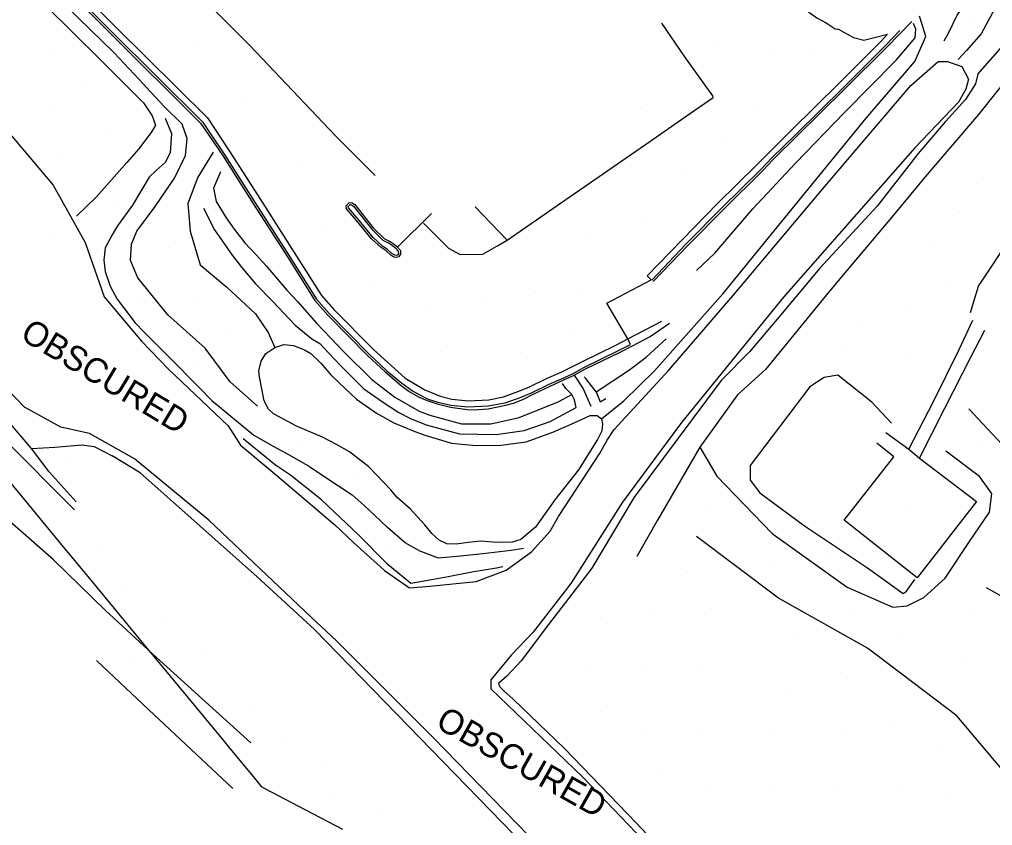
# Model space of a CAD drawing. Extents: x 1497074 to 1501343, y 481943 to 486114.
# Drawn here: x 1497639.7 to 1497875.9, y 483492.4 to 483688.1 of the extents above; entities that cross this region are included whole.
import ezdxf

# ---------------------------------------------------------------- set-up
doc = ezdxf.new("R2010")
doc.units = 0
for name, color, linetype in [('PH Exist DTM Boundary', 7, 'Continuous'), ('PH Exist DTM Breakline', 7, 'Continuous'), ('PH Exist DTM Obscure Area', 7, 'Continuous'), ('PH Exist DTM Obscure Area Text', 7, 'Continuous'), ('PH Exist DTM Point', 7, 'Continuous')]:
    doc.layers.add(name, color=color, linetype=linetype)

msp = doc.modelspace()

# ---------------------------------------------------------------- linework, layer by layer
at = {"layer": 'PH Exist DTM Boundary'}
msp.add_lwpolyline([(1497635.54, 483577.94), (1497640.86, 483571.49), (1497649.09, 483561.53), (1497657.38, 483551.49), (1497669.09, 483537.31), (1497673.9, 483531.49), (1497689.09, 483513.09), (1497690.41, 483511.49), (1497696.7, 483503.88), (1497698.36, 483501.87), (1497698.36, 483501.87), (1497699.1, 483501.48), (1497709.09, 483496.24), (1497718.13, 483491.49)], dxfattribs=at)
at = {"layer": 'PH Exist DTM Breakline'}
for points in [[(1497575.83, 483754.04), (1497585.07, 483744.96), (1497586.7, 483743.97), (1497599.88, 483735.61), (1497612.14, 483727.98), (1497626.37, 483719.13), (1497635.77, 483713.32), (1497637.64, 483711.74), (1497647, 483702.5), (1497663.02, 483686.34), (1497685.28, 483664.21), (1497687.33, 483661.17), (1497690.78, 483656.02), (1497698.2, 483644.4), (1497706.4, 483631.54), (1497713.02, 483621.1), (1497716.03, 483617.69), (1497725.66, 483608.02), (1497733.35, 483601.07), (1497738.1, 483598.17), (1497741.83, 483596.62)], [(1497562.72, 483753.21), (1497568.33, 483746.83), (1497576.49, 483734.94), (1497585.28, 483728.36), (1497589.95, 483725), (1497595.77, 483721.16), (1497600.07, 483718.96), (1497608.17, 483715.58), (1497619.96, 483710.5), (1497628.08, 483707.35), (1497634.62, 483702.1), (1497645.91, 483691.6), (1497659.31, 483678.33), (1497669.77, 483667.86), (1497671.91, 483664.72), (1497672.72, 483662.5), (1497671.65, 483660.67), (1497668.57, 483656.64), (1497665.77, 483653.41)], [(1497574.43, 483752.61), (1497583.83, 483743.37), (1497585.65, 483742.27), (1497598.81, 483733.92), (1497611.09, 483726.28), (1497625.31, 483717.43), (1497634.59, 483711.7), (1497636.29, 483710.26), (1497645.59, 483701.09), (1497661.58, 483684.88), (1497683.66, 483662.93), (1497685.67, 483660.06), (1497689.1, 483654.93), (1497696.51, 483643.32), (1497704.71, 483630.47), (1497711.41, 483619.89), (1497714.57, 483616.32), (1497724.23, 483606.49), (1497728.48, 483602.58), (1497732.36, 483599.27), (1497734.32, 483597.83), (1497736.71, 483596.39), (1497738.66, 483595.59), (1497741.06, 483594.77)], [(1497574.78, 483752.97), (1497584.14, 483743.77), (1497585.91, 483742.7), (1497599.08, 483734.34), (1497611.35, 483726.71), (1497625.58, 483717.86), (1497634.89, 483712.1), (1497636.63, 483710.63), (1497645.94, 483701.44), (1497661.96, 483685.28), (1497684.12, 483663.25), (1497686.08, 483660.34), (1497689.52, 483655.2), (1497696.93, 483643.59), (1497705.14, 483630.73), (1497711.82, 483620.2), (1497714.93, 483616.66), (1497724.58, 483606.85), (1497728.82, 483602.83), (1497732.45, 483599.86), (1497735.09, 483597.98), (1497736.41, 483597.24), (1497738.92, 483595.97), (1497741.25, 483595.24)], [(1497573.64, 483748.1), (1497579.34, 483742.98), (1497587.28, 483736.34), (1497594.04, 483732.42), (1497603.79, 483726.42), (1497613.64, 483720.18), (1497622.91, 483714.91), (1497631.39, 483710.16), (1497639.16, 483703.89), (1497645.22, 483697.29), (1497653.88, 483688.51), (1497662.67, 483680.05), (1497668.76, 483673.59), (1497671.46, 483670.56)], [(1497648.71, 483730.85), (1497650.63, 483727.26), (1497671.76, 483705.81), (1497695.58, 483681.83), (1497716.37, 483659.88), (1497726.06, 483650.26)], [(1497822.93, 483707.95), (1497822.81, 483706.32), (1497824.27, 483704.15), (1497826.17, 483701.49), (1497826.69, 483700.35), (1497827.15, 483698.94), (1497827.87, 483697.45), (1497828.78, 483696.01), (1497829.79, 483694.47), (1497830.42, 483693.29), (1497830.64, 483692.17), (1497830.86, 483690.95), (1497831.3, 483689.86), (1497833.28, 483688.55), (1497834.47, 483687.88), (1497835.51, 483687.3), (1497837.67, 483685.85), (1497838.51, 483685.76), (1497839.63, 483685.13), (1497840.84, 483684.45), (1497842.15, 483683.72), (1497844.7, 483683.08), (1497846.93, 483683.68), (1497850.43, 483684.56)], [(1497864.16, 483682.92), (1497865.32, 483684.98), (1497867.34, 483689.2), (1497869.92, 483692.64), (1497875.5, 483699.15), (1497881.21, 483704.9), (1497885.39, 483706.21), (1497889.4, 483705.65), (1497893.37, 483703.52)], [(1497919.84, 483703.45), (1497916.87, 483699.5), (1497910.38, 483696.91), (1497902.91, 483696.72), (1497899.24, 483695.95), (1497894.07, 483691.67), (1497883.32, 483678.69), (1497872.48, 483665.05), (1497859.56, 483649.91), (1497851.77, 483640.5), (1497840.53, 483627.17), (1497836.36, 483622.13)], [(1497872.34, 483674.87), (1497879.53, 483683.03), (1497887.17, 483692.17), (1497892.8, 483698.81), (1497892.79, 483700.85), (1497891.93, 483702.11), (1497889.19, 483703.47), (1497886.19, 483703.42), (1497884.52, 483702.55), (1497883.4, 483701.73), (1497879.77, 483697.78), (1497877.06, 483691.88), (1497873.13, 483684.66), (1497869.6, 483680.61), (1497867.54, 483678.39)], [(1497780.96, 483591.16), (1497786.43, 483595.5), (1497793.83, 483602.79), (1497800.9, 483610.75), (1497810.53, 483621.57), (1497824.73, 483639.11), (1497845.24, 483664.15), (1497857.07, 483677.91), (1497859.68, 483683.97), (1497858.87, 483686.92), (1497858.2, 483688.91)], [(1497850.27, 483681.44), (1497856.32, 483687.67)], [(1497771.24, 483643.7), (1497792.74, 483658.47), (1497801.51, 483664.67), (1497808.08, 483669.22), (1497807.98, 483669.6), (1497801.17, 483679.02), (1497795.59, 483687.2)], [(1497804.02, 483627.14), (1497808.47, 483631.39), (1497817.74, 483642.14), (1497828.04, 483653.24), (1497839.99, 483665.51), (1497852.48, 483678.24), (1497857.14, 483683.65), (1497857.26, 483685.81), (1497856.74, 483687.15)], [(1497849.91, 483681.79), (1497853.4, 483685.46)], [(1497792.1, 483625.85), (1497800.56, 483634.64), (1497809.24, 483643.49), (1497818.61, 483652.76), (1497821.4, 483655.5), (1497827.12, 483661.26), (1497838.64, 483672.67), (1497848.85, 483682.85)], [(1497848.85, 483682.85), (1497850.43, 483684.56)], [(1497793.19, 483624.82), (1497801.57, 483633.63), (1497810.3, 483642.43), (1497819.68, 483651.71), (1497822.34, 483654.49), (1497828.17, 483660.19), (1497839.7, 483671.61), (1497849.91, 483681.79)], [(1497793.55, 483624.47), (1497801.93, 483633.28), (1497810.66, 483642.07), (1497820.04, 483651.36), (1497822.69, 483654.13), (1497828.52, 483659.84), (1497840.05, 483671.25), (1497850.27, 483681.44)], [(1497872.34, 483674.87), (1497871.78, 483672.46), (1497869.35, 483668.72), (1497864.53, 483663.34), (1497857.88, 483655.56), (1497847.87, 483642.82), (1497833.97, 483627.75), (1497824.05, 483615.85), (1497816.9, 483607.39), (1497810.05, 483600.45), (1497788.88, 483572.14), (1497778.63, 483554.89), (1497768.08, 483541.19), (1497761.44, 483532.36), (1497758.01, 483528.64), (1497756, 483526.9), (1497756.26, 483526.04), (1497757.26, 483525.07), (1497759.55, 483523.07), (1497771.97, 483511.13), (1497789.42, 483493.02), (1497805.35, 483476.14)], [(1497697.42, 483594.25), (1497690.79, 483600.17), (1497684.72, 483608.29), (1497675.69, 483616.38), (1497668.38, 483625.42), (1497666.64, 483629.57), (1497666.87, 483633.56), (1497668.17, 483636.72), (1497672.58, 483642.72), (1497677.31, 483649.62), (1497679.97, 483655.12), (1497680.36, 483659.19), (1497679.13, 483662.71), (1497674.88, 483666.95), (1497671.46, 483670.56)], [(1497675.02, 483664.15), (1497676.55, 483660.43), (1497676.23, 483655.77), (1497675.01, 483653.38), (1497672.87, 483651.44), (1497671.12, 483649.85), (1497667.14, 483643.05), (1497663.49, 483638.04), (1497662.14, 483635.84), (1497660.47, 483632.66), (1497660.12, 483629.67), (1497660.51, 483626.94), (1497661.7, 483623.38), (1497663.41, 483620.18), (1497667.79, 483614.43), (1497669.98, 483612.19), (1497675.96, 483606.23), (1497683.3, 483598.8), (1497686.39, 483595.58), (1497696.53, 483587.21), (1497701.23, 483584.55), (1497705.11, 483582.39), (1497710.06, 483579.59), (1497713.56, 483577.26), (1497720.45, 483572.68), (1497723.38, 483570.09), (1497725.78, 483567.84)], [(1497686.66, 483655.94), (1497682.95, 483649.86), (1497680.51, 483643.44), (1497681.15, 483636.72), (1497683.56, 483628.54), (1497690, 483623.09), (1497696.96, 483616.63), (1497700.02, 483612.12), (1497701.63, 483608.46)], [(1497653.51, 483640.38), (1497658.38, 483645.08), (1497665.77, 483653.41)], [(1497688.51, 483651.11), (1497686.76, 483647.2), (1497687.42, 483643.93), (1497689.87, 483639.95), (1497691.79, 483637.2), (1497694.41, 483633.91), (1497697.14, 483631), (1497699.54, 483628.28), (1497704.6, 483622.39), (1497707.24, 483619.6), (1497709.42, 483617.02), (1497711.82, 483614.36), (1497715.15, 483610.83), (1497718.37, 483607.52), (1497725.25, 483600.71), (1497730.77, 483596.38), (1497736.69, 483593.03), (1497739.33, 483592.03)], [(1497870.59, 483616.98), (1497872.49, 483623.34), (1497881.01, 483636.16), (1497893.02, 483647.38), (1497893.99, 483648.02), (1497908.7, 483636.14), (1497915.18, 483630.74)], [(1497727.48, 483632.76), (1497725.17, 483634.88), (1497721.48, 483639.29), (1497719.07, 483642.15), (1497718.98, 483642.89), (1497719.75, 483643.69), (1497720.43, 483643.61), (1497721.1, 483643.21), (1497725.56, 483637.56), (1497728.22, 483634.92), (1497729.4, 483634.3)], [(1497727.82, 483633.12), (1497725.54, 483635.22), (1497721.87, 483639.61), (1497719.55, 483642.36), (1497719.5, 483642.72), (1497719.94, 483643.17), (1497720.27, 483643.13), (1497720.76, 483642.83), (1497725.18, 483637.23), (1497727.92, 483634.51), (1497729.16, 483633.86)], [(1497750.32, 483642.61), (1497758.09, 483634.57), (1497771.24, 483643.7)], [(1497653.03, 483569.03), (1497635.82, 483586.41), (1497626.83, 483594.18), (1497608.71, 483609.33), (1497587.1, 483627.01), (1497571.53, 483641.23)], [(1497684.34, 483642.29), (1497687.05, 483637.01), (1497691.31, 483630.92), (1497693.55, 483627.99), (1497697.01, 483623.95), (1497701.17, 483619.65), (1497706.64, 483613.88), (1497710.63, 483610.55), (1497712.62, 483609.42), (1497714.78, 483607.08), (1497717.49, 483604.19), (1497720.49, 483601.2), (1497723.3, 483598.47), (1497727.83, 483595.26), (1497731.76, 483592.73), (1497734.63, 483591.22), (1497738.37, 483589.73)], [(1497739.7, 483641.04), (1497731.42, 483632.83)], [(1497737.77, 483638.63), (1497743.82, 483632.63), (1497746.69, 483631.08), (1497752.16, 483631.15), (1497755.6, 483633.12), (1497758.09, 483634.57)], [(1497731.1, 483632.44), (1497730.13, 483633.26), (1497729.16, 483633.86)], [(1497731.42, 483632.83), (1497730.42, 483633.67), (1497729.4, 483634.3)], [(1497731.42, 483632.83), (1497732.14, 483632.02), (1497732.18, 483631.16), (1497731.74, 483630.49), (1497731.14, 483630.3), (1497730.58, 483630.41), (1497729.81, 483630.89), (1497728.71, 483631.91), (1497727.48, 483632.76)], [(1497731.1, 483632.44), (1497731.65, 483631.82), (1497731.67, 483631.3), (1497731.42, 483630.91), (1497731.11, 483630.82), (1497730.77, 483630.88), (1497730.11, 483631.29), (1497729.02, 483632.3), (1497727.82, 483633.12)], [(1497787.33, 483610.55), (1497782.31, 483619.23), (1497793.06, 483624.94)], [(1497793.06, 483624.94), (1497792.1, 483625.85)], [(1497836.36, 483622.13), (1497830.19, 483614.66), (1497820.83, 483603.11), (1497813.98, 483596.95), (1497804.83, 483584.31), (1497794.55, 483566.53), (1497789.53, 483557.76)], [(1497653.44, 483571.02), (1497646.88, 483578.26), (1497642.57, 483583.92), (1497636.49, 483591.1), (1497628.04, 483600.75), (1497622.39, 483606.96), (1497615.79, 483613.28), (1497609.03, 483619.16)], [(1497788.01, 483609.21), (1497787.33, 483610.55), (1497795.61, 483614.83)], [(1497788.47, 483608.87), (1497792.77, 483611.17), (1497797.49, 483614.38)], [(1497855.56, 483583.75), (1497861.62, 483595.35), (1497867.83, 483608.02), (1497871.17, 483615.1)], [(1497858.21, 483581.57), (1497864.32, 483593.74), (1497870.75, 483606.32), (1497874.02, 483612.71)], [(1497741.83, 483596.62), (1497744.61, 483595.93), (1497748.72, 483595.52), (1497753.59, 483595.73), (1497757.17, 483596.49), (1497760.94, 483597.85), (1497763.53, 483598.95), (1497767.65, 483600.93), (1497771.2, 483602.51), (1497773.49, 483603.64), (1497776.35, 483605.04), (1497784.46, 483609.08), (1497787.33, 483610.55)], [(1497779.71, 483597.68), (1497787.56, 483602.93), (1497791.83, 483606.15), (1497796.65, 483610.54)], [(1497729.84, 483573.91), (1497724.48, 483579.48), (1497719.79, 483583.12), (1497716.61, 483584.89), (1497713.26, 483586.68), (1497706.89, 483589.38), (1497703.06, 483591.45), (1497701.36, 483592.4), (1497700.12, 483593.48), (1497699.05, 483595.51), (1497697.92, 483601.35), (1497697.79, 483602.83), (1497698.37, 483605.17), (1497699.45, 483606.99), (1497701.63, 483608.46), (1497703.86, 483609.19), (1497706.17, 483608.95), (1497708.85, 483607.88), (1497710.44, 483606.99), (1497712.81, 483604.71), (1497715.29, 483601.82), (1497718.8, 483598.46), (1497721.52, 483595.93), (1497726.38, 483592.55), (1497730.53, 483590.22), (1497735.24, 483588.26), (1497738.05, 483587.15)], [(1497741.06, 483594.77), (1497744.28, 483593.95), (1497748.39, 483593.39), (1497750.06, 483593.37), (1497753.43, 483593.6), (1497757.76, 483594.51), (1497759.63, 483594.94), (1497761.9, 483595.86), (1497764.36, 483597.12), (1497768.49, 483599.11), (1497772.02, 483600.69), (1497774.33, 483601.74), (1497776.95, 483603.22), (1497785.35, 483607.29), (1497788.47, 483608.87)], [(1497741.25, 483595.24), (1497744.36, 483594.44), (1497748.52, 483594.1), (1497753.48, 483594.28), (1497757.56, 483595.04), (1497761.49, 483596.45), (1497764.15, 483597.58), (1497768.28, 483599.57), (1497771.81, 483601.14), (1497774.1, 483602.19), (1497776.72, 483603.66), (1497785.13, 483607.74), (1497788.01, 483609.21)], [(1497774.33, 483601.74), (1497776.53, 483598.42), (1497778.41, 483594.22)], [(1497779.71, 483597.68), (1497778.54, 483599.13), (1497777.19, 483600.91), (1497776.76, 483601.37)], [(1497851.4, 483590.07), (1497846.61, 483595.19), (1497838.33, 483601.79), (1497835.04, 483601.22), (1497831.52, 483598.89), (1497817.08, 483579.86), (1497817.11, 483576.3), (1497819.39, 483573.19), (1497830.28, 483565.18), (1497845.52, 483555), (1497854.21, 483548.72), (1497855.04, 483549.33), (1497857.03, 483552.15)], [(1497773.79, 483597.04), (1497772.33, 483598.54), (1497771.5, 483599.72)], [(1497739.33, 483592.03), (1497746.97, 483589.94), (1497754.08, 483589.92), (1497761.01, 483591.47), (1497770.47, 483595.3), (1497773.79, 483597.04)], [(1497774.81, 483593.89), (1497774.4, 483595.73), (1497773.79, 483597.04)], [(1497779.71, 483597.68), (1497780.67, 483595.32), (1497782.01, 483596.1)], [(1497738.37, 483589.73), (1497746.49, 483587.55), (1497755.41, 483587.37), (1497762.23, 483588.31), (1497768.52, 483590.51), (1497774.81, 483593.89)], [(1497870.14, 483593.58), (1497882.86, 483579.97), (1497900.81, 483562.68), (1497904.72, 483560.47), (1497911.47, 483560.2), (1497919.11, 483563.86), (1497924.12, 483566.61), (1497932.68, 483578.31), (1497941.22, 483590.2)], [(1497738.05, 483587.15), (1497744.57, 483585.21), (1497750.43, 483584.72), (1497756.51, 483584.77), (1497762.68, 483585.54), (1497769.13, 483587.89), (1497774.35, 483590.18), (1497778.24, 483592), (1497779.89, 483591.93), (1497780.96, 483591.16), (1497781.21, 483589.89), (1497781.06, 483588.24), (1497780, 483586.1), (1497775.37, 483578.81), (1497769.61, 483571.49), (1497764.92, 483564.81), (1497761.39, 483561.83), (1497759.29, 483561.2), (1497755.52, 483561.16), (1497751.7, 483561.48), (1497748.61, 483561.14), (1497745.67, 483560.72), (1497743.46, 483560.79), (1497741.53, 483561.73), (1497739.8, 483563.33), (1497738.07, 483565.4), (1497734.61, 483569.21), (1497731.32, 483572.15), (1497729.84, 483573.91)], [(1497722.08, 483562.88), (1497712.96, 483571.45), (1497705.49, 483577.46), (1497701.84, 483579.94), (1497693.98, 483586.26)], [(1497849.97, 483587.84), (1497855.56, 483583.75), (1497858.21, 483581.57), (1497872.05, 483571.05), (1497857.6, 483552.55), (1497839.88, 483566.51), (1497851.97, 483581.91), (1497847.82, 483585.24)], [(1497642.57, 483583.92), (1497648.28, 483584.28), (1497654.89, 483584.86), (1497657.78, 483584.44), (1497662.18, 483582.15)], [(1497804.83, 483584.31), (1497808.94, 483577.2), (1497822.39, 483563.34), (1497840.59, 483550.27), (1497851.72, 483545.43), (1497855.15, 483545.72), (1497859.22, 483547.76), (1497864.43, 483552.49), (1497870.35, 483561.37), (1497875.18, 483568.49), (1497875.75, 483572.98), (1497874.7, 483574.52), (1497872.75, 483577.15), (1497864.57, 483583.31)], [(1497711.3, 483540.01), (1497697.26, 483552.86), (1497668.95, 483578.07), (1497662.18, 483582.15)], [(1497695.85, 483512.46), (1497672.06, 483534.05), (1497660.51, 483544.69), (1497647.91, 483556.93), (1497632.56, 483570.39)], [(1497736.61, 483559.16), (1497733.3, 483561.05), (1497729.06, 483564.77), (1497725.78, 483567.84)], [(1497722.08, 483562.88), (1497728.68, 483556.23), (1497734.68, 483551.27)], [(1498015.45, 483385.93), (1498002.38, 483393.3), (1497973.49, 483412.44), (1497944.51, 483436.4), (1497919.03, 483459.44), (1497900.69, 483480.31), (1497884.28, 483498.85), (1497867.21, 483519), (1497845.52, 483535.49), (1497823.94, 483547.65), (1497804.03, 483562.57)], [(1497736.61, 483559.16), (1497741.34, 483557.44), (1497746.78, 483557.85), (1497752.15, 483558.47), (1497759.01, 483559.28), (1497762.04, 483559.79)], [(1497734.68, 483551.27), (1497740.17, 483552.25), (1497743.77, 483552.87), (1497749.51, 483554.01), (1497755.45, 483554.97), (1497757.03, 483555.28)], [(1497874.34, 483550.2), (1497884.59, 483544.42), (1497899.91, 483535.79), (1497914.61, 483526.27), (1497930.41, 483512.95), (1497937.69, 483507.58), (1497951.32, 483499.75), (1497966.68, 483491.09), (1497977.43, 483485.56), (1497994.05, 483476.2), (1498010.11, 483469.1), (1498024.5, 483466.16), (1498037, 483468.14), (1498046.25, 483468.23), (1498050, 483466.58), (1498058.85, 483464.91), (1498068.27, 483463.72)], [(1497799.15, 483447.56), (1497765.16, 483479.81), (1497765.38, 483484.37), (1497711.3, 483540.01)], [(1497691.43, 483501.39), (1497671.08, 483520.52), (1497658.4, 483532.49)]]:
    msp.add_lwpolyline(points, dxfattribs=at)
at = {"layer": 'PH Exist DTM Obscure Area'}
for points in [[(1497720.75, 483561.16), (1497728.27, 483554.3), (1497734.4, 483550.1), (1497739.31, 483550.53), (1497750.51, 483551.64), (1497757.86, 483554.38), (1497763.98, 483558.86), (1497768.52, 483563.91), (1497770.53, 483567.46), (1497780.47, 483582.62), (1497782.35, 483585.95), (1497784.03, 483588.6), (1497797.29, 483602.99), (1497812.84, 483621.05), (1497835.13, 483647.5), (1497856.06, 483672.07), (1497862.73, 483677.95), (1497865, 483677.91), (1497868.49, 483676.73), (1497870.06, 483673.67), (1497869.45, 483671.19), (1497867.66, 483668.03), (1497857.08, 483656.93), (1497825.13, 483620.69), (1497800.4, 483590.28), (1497786.06, 483570.89), (1497773.54, 483551.2), (1497764.35, 483539.33), (1497759.11, 483533.86), (1497754.08, 483527.78), (1497754.14, 483525.59), (1497776.34, 483504.23), (1497806.12, 483473.16)], [(1497635.22, 483662.83), (1497647.82, 483647.93), (1497655.6, 483633.98), (1497660.22, 483620.79), (1497669.3, 483610.04), (1497675.85, 483603.21), (1497690.33, 483589.47), (1497693.34, 483584.8), (1497702.16, 483577.4), (1497716.25, 483565.4), (1497720.75, 483561.16)], [(1497710.48, 483542.97), (1497685.64, 483566.53), (1497667.62, 483581.43), (1497656.65, 483587.58), (1497649.72, 483589.1), (1497640.91, 483594.01), (1497636.77, 483598.24)], [(1497766.17, 483486.95), (1497740.14, 483513.76), (1497716.66, 483537.23), (1497710.48, 483542.97)]]:
    msp.add_lwpolyline(points, dxfattribs=at)
at = {"layer": 'PH Exist DTM Point'}
for p, q in [((1497870.81, 483687.76), (1497870.81, 483687.76)), ((1497647.15, 483681.19), (1497647.15, 483681.19)), ((1497682.84, 483682.14), (1497682.84, 483682.14)), ((1497808.87, 483682.76), (1497808.87, 483682.76)), ((1497821.89, 483679.87), (1497821.89, 483679.87)), ((1497832.03, 483679.51), (1497832.03, 483679.51)), ((1497655.85, 483672.79), (1497655.85, 483672.79)), ((1497694.5, 483668.73), (1497694.5, 483668.73)), ((1497648.04, 483666.66), (1497648.04, 483666.66)), ((1497790.33, 483666.4), (1497790.33, 483666.4)), ((1497817.94, 483667.09), (1497817.94, 483667.09)), ((1497869.63, 483665.55), (1497869.63, 483665.55)), ((1497660.5, 483660.44), (1497660.5, 483660.44)), ((1497810.24, 483657.99), (1497810.24, 483657.99)), ((1497649.5, 483654.33), (1497649.5, 483654.33)), ((1497708.48, 483653.99), (1497708.48, 483653.99)), ((1497800.52, 483650.26), (1497800.52, 483650.26)), ((1497679.41, 483649.01), (1497679.41, 483649.01)), ((1497872.05, 483648.34), (1497872.05, 483648.34)), ((1497662.7, 483643.48), (1497662.7, 483643.48)), ((1497867.87, 483641.19), (1497867.87, 483641.19)), ((1497713.89, 483638.27), (1497713.89, 483638.27)), ((1497790.48, 483639.13), (1497790.48, 483639.13)), ((1497777.16, 483636.15), (1497777.16, 483636.15)), ((1497647.72, 483634.58), (1497647.72, 483634.58)), ((1497675.79, 483632.68), (1497675.79, 483632.68)), ((1497722.79, 483632.91), (1497722.79, 483632.91)), ((1497861.21, 483633.07), (1497861.21, 483633.07)), ((1497864.9, 483624.59), (1497864.9, 483624.59)), ((1497724.31, 483623.27), (1497724.31, 483623.27)), ((1497764.96, 483621.76), (1497764.96, 483621.76)), ((1497776.14, 483622.57), (1497776.14, 483622.57)), ((1497668.87, 483619.04), (1497668.87, 483619.04)), ((1497682.23, 483620.19), (1497682.23, 483620.19)), ((1497752.91, 483619.46), (1497752.91, 483619.46)), ((1497739.43, 483618.96), (1497739.43, 483618.96)), ((1497855.46, 483618.4), (1497855.46, 483618.4)), ((1497844.14, 483614.61), (1497844.14, 483614.61)), ((1497691.1, 483612.93), (1497691.1, 483612.93)), ((1497773.61, 483613.02), (1497773.61, 483613.02)), ((1497822.64, 483610.24), (1497822.64, 483610.24)), ((1497741.81, 483607.53), (1497741.81, 483607.53)), ((1497840.17, 483608.5), (1497840.17, 483608.5)), ((1497682.16, 483605.38), (1497682.16, 483605.38)), ((1497761.28, 483607.15), (1497761.28, 483607.15)), ((1497855.41, 483605.49), (1497855.41, 483605.49)), ((1497809.19, 483594.71), (1497809.19, 483594.71)), ((1497646.76, 483588.88), (1497646.76, 483588.88)), ((1497707.15, 483585.76), (1497707.15, 483585.76)), ((1497872.22, 483584.19), (1497872.22, 483584.19)), ((1497650.96, 483580.25), (1497650.96, 483580.25)), ((1497721.83, 483576.63), (1497721.83, 483576.63)), ((1497807.08, 483570.45), (1497807.08, 483570.45)), ((1497855.83, 483568.66), (1497855.83, 483568.66)), ((1497729.43, 483560.4), (1497729.43, 483560.4)), ((1497658.82, 483559.59), (1497658.82, 483559.59)), ((1497822.17, 483556.45), (1497822.17, 483556.45)), ((1497836.43, 483557.51), (1497836.43, 483557.51)), ((1497801.84, 483553.85), (1497801.84, 483553.85)), ((1497664.71, 483550.93), (1497664.71, 483550.93)), ((1497793.67, 483544.88), (1497793.67, 483544.88)), ((1497807.67, 483545.01), (1497807.67, 483545.01)), ((1497841.11, 483545.2), (1497841.11, 483545.2)), ((1497870.51, 483544.28), (1497870.51, 483544.28)), ((1497675.36, 483542.54), (1497675.36, 483542.54)), ((1497782.39, 483541.37), (1497782.39, 483541.37)), ((1497828.34, 483537.81), (1497828.34, 483537.81)), ((1497853.3, 483538.24), (1497853.3, 483538.24)), ((1497666.85, 483532.28), (1497666.85, 483532.28)), ((1497684.6, 483533.75), (1497684.6, 483533.75)), ((1497868.43, 483533.26), (1497868.43, 483533.26)), ((1497777.86, 483530.11), (1497777.86, 483530.11)), ((1497791.44, 483529.9), (1497791.44, 483529.9)), ((1497805.58, 483530.12), (1497805.58, 483530.12)), ((1497838.96, 483529.53), (1497838.96, 483529.53)), ((1497825.85, 483524.56), (1497825.85, 483524.56)), ((1497679.97, 483519.98), (1497679.97, 483519.98)), ((1497696.27, 483521.58), (1497696.27, 483521.58)), ((1497780.74, 483520.14), (1497780.74, 483520.14)), ((1497791.94, 483515.66), (1497791.94, 483515.66)), ((1497805.52, 483515.63), (1497805.52, 483515.63)), ((1497822.93, 483515.43), (1497822.93, 483515.43)), ((1497839.75, 483515.54), (1497839.75, 483515.54)), ((1497851.84, 483516.86), (1497851.84, 483516.86)), ((1497704.56, 483513.81), (1497704.56, 483513.81)), ((1497863.58, 483511.05), (1497863.58, 483511.05)), ((1497712.88, 483507.98), (1497712.88, 483507.98)), ((1497795.07, 483504.66), (1497795.07, 483504.66)), ((1497806.36, 483501.91), (1497806.36, 483501.91)), ((1497821.57, 483502.17), (1497821.57, 483502.17)), ((1497838.09, 483501.67), (1497838.09, 483501.67)), ((1497852.75, 483501.08), (1497852.75, 483501.08)), ((1497701.39, 483499.25), (1497701.39, 483499.25)), ((1497715.36, 483499.77), (1497715.36, 483499.77)), ((1497865.33, 483500.38), (1497865.33, 483500.38)), ((1497726.76, 483496.3), (1497726.76, 483496.3))]:
    msp.add_line(p, q, dxfattribs=at)

# ---------------------------------------------------------------- texts
at = {"layer": 'PH Exist DTM Obscure Area Text'}
for rotation, p in [(328.8585, (1497639.53, 483610.69)), (330.5957, (1497740.38, 483516.39))]:
    msp.add_text('OBSCURED', height=6, rotation=rotation, dxfattribs=at).set_placement(p)

doc.saveas('drawing.dxf')
